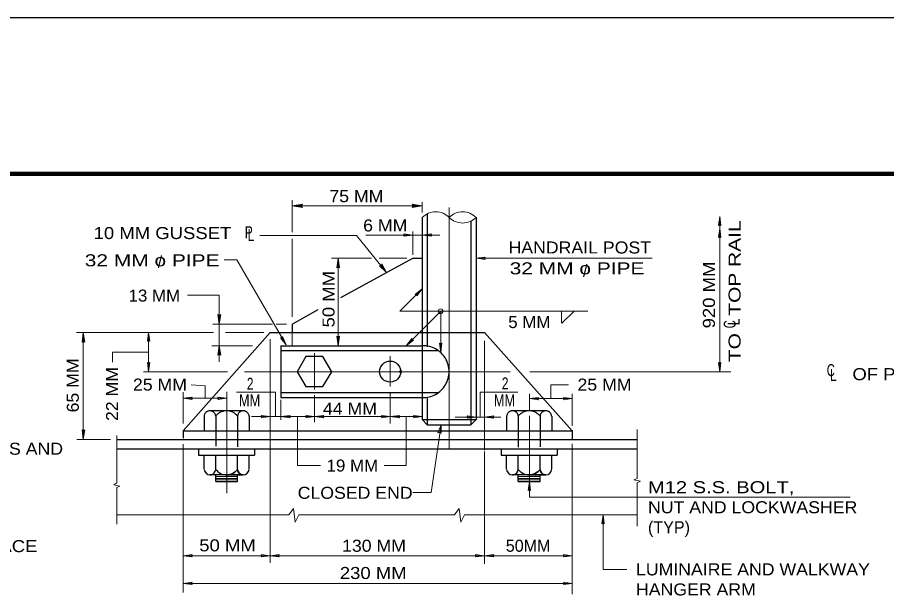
# Model space of a CAD drawing. Extents: x 312601.858 to 312602.699, y 144420.109 to 144420.704.
# Drawn here: x 312602.2633 to 312602.4801, y 144420.5593 to 144420.7035 of the extents above; entities that cross this region are included whole.
import ezdxf
from ezdxf.enums import TextEntityAlignment as Align

# ---------------------------------------------------------------- set-up
doc = ezdxf.new("R2010")
doc.units = 0
doc.header["$LTSCALE"] = 0.0012
doc.header["$PDMODE"] = 32
doc.header["$PDSIZE"] = 0.0006
for name, pattern in [('DOT_DASHED', [7.7, 5, -1.2, 0.3, -1.2]), ('LONG_DASHED', [7.5, 6, -1.5]), ('MEDIUM_DASHED', [4.5, 3, -1.5])]:
    doc.linetypes.add(name, pattern=pattern)
for name, color, linetype, lineweight in [('1', 7, 'Continuous', 13), ('2', 7, 'Continuous', 13), ('39', 7, 'Continuous', 13), ('4', 7, 'Continuous', 13)]:
    doc.layers.add(name, color=color, linetype=linetype, lineweight=lineweight)

msp = doc.modelspace()

# ---------------------------------------------------------------- hatches: boundary and pattern name
at = {"layer": '39'}
for points in [[(312602.3341, 144420.6565), (312602.3344, 144420.6561), (312602.3318, 144420.6565), (312602.3344, 144420.6569)], [(312602.3341, 144420.6565), (312602.3344, 144420.6561), (312602.3318, 144420.6565), (312602.3344, 144420.6569)], [(312602.362, 144420.6565), (312602.3618, 144420.6569), (312602.3643, 144420.6565), (312602.3618, 144420.6561)], [(312602.3433, 144420.6412), (312602.343, 144420.641), (312602.3433, 144420.6434), (312602.3436, 144420.641)], [(312602.354, 144420.6416), (312602.3542, 144420.642), (312602.3554, 144420.6399), (312602.3536, 144420.6415)], [(312602.3136, 144420.6292), (312602.314, 144420.6294), (312602.3136, 144420.627), (312602.3133, 144420.6294)], [(312602.2797, 144420.6227), (312602.2794, 144420.6225), (312602.2797, 144420.6249), (312602.2801, 144420.6225)], [(312602.3433, 144420.6238), (312602.3436, 144420.624), (312602.3433, 144420.6216), (312602.343, 144420.624)], [(312602.3433, 144420.6238), (312602.3436, 144420.624), (312602.3433, 144420.6216), (312602.343, 144420.624)], [(312602.3136, 144420.6194), (312602.3133, 144420.6192), (312602.3136, 144420.6216), (312602.314, 144420.6192)], [(312602.2797, 144420.6004), (312602.2801, 144420.6006), (312602.2797, 144420.5982), (312602.2794, 144420.6006)]]:
    msp.add_hatch(color=256, dxfattribs=at).paths.add_polyline_path(points)

# ---------------------------------------------------------------- linework, layer by layer
at = {"layer": '1'}
for p, q in [((312602.3318, 144420.6579), (312602.3318, 144420.6499)), ((312602.3318, 144420.6565), (312602.3643, 144420.6565)), ((312602.3643, 144420.6548), (312602.3643, 144420.6574)), ((312602.3619, 144420.6443), (312602.3619, 144420.6501)), ((312602.4385, 144420.6508), (312602.4385, 144420.6151)), ((312602.3238, 144420.6491), (312602.3479, 144420.6491)), ((312602.3318, 144420.6483), (312602.3318, 144420.6288)), ((312602.3479, 144420.6491), (312602.3554, 144420.6399)), ((312602.3416, 144420.6434), (312602.3516, 144420.6434)), ((312602.3433, 144420.6434), (312602.3433, 144420.6216)), ((312602.3535, 144420.6434), (312602.3604, 144420.6434)), ((312602.3777, 144420.6434), (312602.4216, 144420.6434)), ((312602.3149, 144420.643), (312602.318, 144420.643)), ((312602.318, 144420.643), (312602.3303, 144420.6218)), ((312602.3587, 144420.6302), (312602.3643, 144420.6358)), ((312602.3587, 144420.6302), (312602.4056, 144420.6302)), ((312602.3689, 144420.6302), (312602.3603, 144420.6216)), ((312602.3689, 144420.6301), (312602.3689, 144420.6199)), ((312602.399, 144420.6302), (312602.399, 144420.6272)), ((312602.3991, 144420.6272), (312602.4022, 144420.6302)), ((312602.3269, 144420.627), (312602.312, 144420.627)), ((312602.3304, 144420.627), (312602.3278, 144420.627)), ((312602.278, 144420.6249), (312602.3122, 144420.6249)), ((312602.2797, 144420.6249), (312602.2797, 144420.5982)), ((312602.296, 144420.6249), (312602.296, 144420.6152)), ((312602.3152, 144420.6249), (312602.3248, 144420.6249)), ((312602.3263, 144420.6232), (312602.3263, 144420.5952)), ((312602.3798, 144420.6228), (312602.3798, 144420.5955)), ((312602.287, 144420.62), (312602.287, 144420.6175)), ((312602.3118, 144420.6216), (312602.3219, 144420.6216)), ((312602.3136, 144420.6216), (312602.3136, 144420.6176)), ((312602.2947, 144420.6151), (312602.3157, 144420.6151)), ((312602.3911, 144420.6151), (312602.4413, 144420.6151)), ((312602.3046, 144420.61), (312602.3046, 144420.6022)), ((312602.3179, 144420.61), (312602.3277, 144420.61)), ((312602.3563, 144420.6097), (312602.3563, 144420.6022)), ((312602.3787, 144420.61), (312602.3881, 144420.61)), ((312602.391, 144420.6096), (312602.391, 144420.6055)), ((312602.4017, 144420.6096), (312602.4017, 144420.6016)), ((312602.3046, 144420.6085), (312602.3155, 144420.6085)), ((312602.329, 144420.6081), (312602.329, 144420.6031)), ((312602.391, 144420.6084), (312602.4017, 144420.6084)), ((312602.3563, 144420.6039), (312602.3643, 144420.6039)), ((312602.4179, 144420.6007), (312602.4179, 144420.5885)), ((312602.2781, 144420.5982), (312602.2865, 144420.5982)), ((312602.2881, 144420.5992), (312602.2881, 144420.5874)), ((312602.3046, 144420.597), (312602.3046, 144420.56)), ((312602.4017, 144420.5971), (312602.4017, 144420.5596)), ((312602.3263, 144420.5952), (312602.3263, 144420.5674)), ((312602.3798, 144420.5952), (312602.3798, 144420.5672)), ((312602.3155, 144420.5894), (312602.3196, 144420.5894)), ((312602.2873, 144420.5869), (312602.2881, 144420.5874)), ((312602.3128, 144420.589), (312602.3182, 144420.589)), ((312602.3128, 144420.5885), (312602.3182, 144420.5885)), ((312602.3128, 144420.5881), (312602.3182, 144420.5881)), ((312602.3882, 144420.589), (312602.3937, 144420.589)), ((312602.3882, 144420.5885), (312602.3937, 144420.5885)), ((312602.3882, 144420.5881), (312602.3937, 144420.5881)), ((312602.391, 144420.5877), (312602.391, 144420.5838)), ((312602.4171, 144420.5881), (312602.4179, 144420.5885)), ((312602.4171, 144420.5881), (312602.4187, 144420.5878)), ((312602.4179, 144420.5874), (312602.4187, 144420.5878)), ((312602.4179, 144420.5874), (312602.4179, 144420.5766)), ((312602.2873, 144420.5869), (312602.2888, 144420.5866)), ((312602.2881, 144420.5862), (312602.2888, 144420.5866)), ((312602.2881, 144420.5862), (312602.2881, 144420.5771)), ((312602.391, 144420.5838), (312602.471, 144420.5838)), ((312602.2881, 144420.5794), (312602.331, 144420.5794)), ((312602.3335, 144420.5794), (312602.3723, 144420.5794)), ((312602.3748, 144420.5794), (312602.4179, 144420.5794)), ((312602.4094, 144420.5794), (312602.4094, 144420.5658)), ((312602.4094, 144420.5658), (312602.4153, 144420.5658)), ((312602.3046, 144420.5623), (312602.4017, 144420.5623))]:
    msp.add_line(p, q, dxfattribs=at)
at = {"layer": '1', "linetype": 'LONG_DASHED', "lineweight": 25}
for p, q in [((312602.3655, 144420.6545), (312602.3655, 144420.6213)), ((312602.3764, 144420.6527), (312602.3764, 144420.6249)), ((312602.3643, 144420.6249), (312602.3643, 144420.6032)), ((312602.3764, 144420.6249), (312602.3764, 144420.6019)), ((312602.3777, 144420.6249), (312602.3777, 144420.6032)), ((312602.329, 144420.6216), (312602.329, 144420.6087)), ((312602.329, 144420.6216), (312602.3642, 144420.6216)), ((312602.329, 144420.6204), (312602.3683, 144420.6204)), ((312602.329, 144420.6099), (312602.3682, 144420.6099)), ((312602.329, 144420.6087), (312602.3643, 144420.6087)), ((312602.3655, 144420.6088), (312602.3655, 144420.6019)), ((312602.3128, 144420.604), (312602.3128, 144420.5965)), ((312602.3182, 144420.604), (312602.3182, 144420.5964)), ((312602.3643, 144420.6032), (312602.3655, 144420.6019)), ((312602.3643, 144420.6032), (312602.3777, 144420.6032)), ((312602.3764, 144420.6019), (312602.3777, 144420.6032)), ((312602.3882, 144420.604), (312602.3882, 144420.5963)), ((312602.3937, 144420.604), (312602.3937, 144420.5964)), ((312602.3046, 144420.6004), (312602.4016, 144420.6004)), ((312602.3655, 144420.6019), (312602.3764, 144420.6019))]:
    msp.add_line(p, q, dxfattribs=at)
at = {"layer": '1', "linetype": 'DOT_DASHED'}
for p, q in [((312602.371, 144420.6561), (312602.371, 144420.5959)), ((312602.3563, 144420.619), (312602.3563, 144420.6114)), ((312602.3199, 144420.6151), (312602.3862, 144420.6151)), ((312602.3155, 144420.6101), (312602.3155, 144420.5848)), ((312602.391, 144420.6041), (312602.391, 144420.5877))]:
    msp.add_line(p, q, dxfattribs=at)
at = {"layer": '1', "lineweight": 25}
for p, q in [((312602.3643, 144420.6536), (312602.3643, 144420.6249)), ((312602.3777, 144420.6536), (312602.3777, 144420.6249)), ((312602.344, 144420.6336), (312602.3619, 144420.6434)), ((312602.3619, 144420.6434), (312602.3643, 144420.6434)), ((312602.3318, 144420.627), (312602.3383, 144420.6306)), ((312602.3318, 144420.627), (312602.3318, 144420.6249)), ((312602.3046, 144420.6004), (312602.3263, 144420.6249)), ((312602.3263, 144420.6249), (312602.3798, 144420.6249)), ((312602.3798, 144420.6249), (312602.4017, 144420.6004)), ((312602.3046, 144420.6004), (312602.3046, 144420.5985)), ((312602.4017, 144420.6005), (312602.4017, 144420.5982)), ((312602.2881, 144420.5982), (312602.4179, 144420.5982)), ((312602.2881, 144420.5959), (312602.4179, 144420.5959)), ((312602.3224, 144420.5959), (312602.3224, 144420.5943)), ((312602.3979, 144420.5959), (312602.3979, 144420.5943)), ((312602.3099, 144420.5908), (312602.3099, 144420.5943)), ((312602.3128, 144420.5908), (312602.3128, 144420.5943)), ((312602.3182, 144420.5908), (312602.3182, 144420.5943)), ((312602.3211, 144420.5908), (312602.3211, 144420.5943)), ((312602.3853, 144420.5908), (312602.3853, 144420.5943)), ((312602.3882, 144420.5908), (312602.3882, 144420.5943)), ((312602.3937, 144420.5908), (312602.3937, 144420.5943)), ((312602.3966, 144420.5908), (312602.3966, 144420.5943)), ((312602.3128, 144420.5877), (312602.3128, 144420.5894)), ((312602.3182, 144420.5877), (312602.3182, 144420.5894)), ((312602.3882, 144420.5877), (312602.3882, 144420.5894)), ((312602.391, 144420.5894), (312602.3951, 144420.5894)), ((312602.3937, 144420.5877), (312602.3937, 144420.5894)), ((312602.3128, 144420.5877), (312602.3182, 144420.5877)), ((312602.3882, 144420.5877), (312602.3937, 144420.5877))]:
    msp.add_line(p, q, dxfattribs=at)
at = {"layer": '1', "linetype": 'LONG_DASHED'}
msp.add_line((312602.3318, 144420.6249), (312602.3318, 144420.6216), dxfattribs=at)
at = {"layer": '1', "linetype": 'MEDIUM_DASHED', "lineweight": 25}
for p, q in [((312602.3113, 144420.6054), (312602.3196, 144420.6054)), ((312602.3868, 144420.6054), (312602.3951, 144420.6054)), ((312602.3099, 144420.604), (312602.3099, 144420.6004)), ((312602.3211, 144420.604), (312602.3211, 144420.6004)), ((312602.3853, 144420.604), (312602.3853, 144420.6004)), ((312602.3966, 144420.604), (312602.3966, 144420.6004))]:
    msp.add_line(p, q, dxfattribs=at)
at = {"layer": '1'}
for points in [[(312602.4382, 144420.6516), (312602.4385, 144420.6538), (312602.4388, 144420.6516), (312602.4385, 144420.6518)], [(312602.4382, 144420.6486), (312602.4385, 144420.6508), (312602.4388, 144420.6486), (312602.4385, 144420.6488)], [(312602.3597, 144420.6495), (312602.3619, 144420.6492), (312602.3597, 144420.6489), (312602.3599, 144420.6492)], [(312602.3666, 144420.6489), (312602.3643, 144420.6492), (312602.3666, 144420.6495), (312602.3663, 144420.6492)], [(312602.38, 144420.6431), (312602.3777, 144420.6434), (312602.38, 144420.6437), (312602.3797, 144420.6434)], [(312602.3625, 144420.6344), (312602.3643, 144420.6358), (312602.3629, 144420.634), (312602.3629, 144420.6344)], [(312602.2957, 144420.6227), (312602.296, 144420.6249), (312602.2963, 144420.6227), (312602.296, 144420.6229)], [(312602.3294, 144420.6239), (312602.3303, 144420.6218), (312602.3289, 144420.6236), (312602.3293, 144420.6236)], [(312602.3621, 144420.623), (312602.3603, 144420.6216), (312602.3617, 144420.6234), (312602.3617, 144420.623)], [(312602.3692, 144420.6222), (312602.3689, 144420.6199), (312602.3686, 144420.6222), (312602.3689, 144420.6219)], [(312602.2963, 144420.6174), (312602.296, 144420.6151), (312602.2957, 144420.6174), (312602.296, 144420.6171)], [(312602.4388, 144420.6174), (312602.4385, 144420.6151), (312602.4382, 144420.6174), (312602.4385, 144420.6171)], [(312602.3069, 144420.6082), (312602.3046, 144420.6085), (312602.3069, 144420.6088), (312602.3066, 144420.6085)], [(312602.3133, 144420.6088), (312602.3155, 144420.6085), (312602.3133, 144420.6082), (312602.3135, 144420.6085)], [(312602.3933, 144420.6081), (312602.391, 144420.6084), (312602.3933, 144420.6087), (312602.393, 144420.6084)], [(312602.3995, 144420.6087), (312602.4017, 144420.6084), (312602.3995, 144420.6081), (312602.3997, 144420.6084)], [(312602.3241, 144420.6042), (312602.3263, 144420.6039), (312602.3241, 144420.6036), (312602.3243, 144420.6039)], [(312602.3313, 144420.6036), (312602.329, 144420.6039), (312602.3313, 144420.6042), (312602.331, 144420.6039)], [(312602.3352, 144420.6042), (312602.3374, 144420.6039), (312602.3352, 144420.6036), (312602.3354, 144420.6039)], [(312602.3397, 144420.6036), (312602.3374, 144420.6039), (312602.3397, 144420.6042), (312602.3394, 144420.6039)], [(312602.3541, 144420.6042), (312602.3563, 144420.6039), (312602.3541, 144420.6036), (312602.3543, 144420.6039)], [(312602.3586, 144420.6036), (312602.3563, 144420.6039), (312602.3586, 144420.6042), (312602.3583, 144420.6039)], [(312602.3621, 144420.6042), (312602.3643, 144420.6039), (312602.3621, 144420.6036), (312602.3623, 144420.6039)], [(312602.3755, 144420.6041), (312602.3777, 144420.6038), (312602.3755, 144420.6035), (312602.3757, 144420.6038)], [(312602.3821, 144420.6035), (312602.3798, 144420.6038), (312602.3821, 144420.6041), (312602.3818, 144420.6038)], [(312602.3682, 144420.5999), (312602.369, 144420.6019), (312602.369, 144420.5998), (312602.3687, 144420.6)], [(312602.3907, 144420.5855), (312602.391, 144420.5877), (312602.3913, 144420.5855), (312602.391, 144420.5857)], [(312602.4091, 144420.5772), (312602.4094, 144420.5794), (312602.4097, 144420.5772), (312602.4094, 144420.5774)], [(312602.3069, 144420.5689), (312602.3046, 144420.5692), (312602.3069, 144420.5695), (312602.3066, 144420.5692)], [(312602.3241, 144420.5695), (312602.3263, 144420.5692), (312602.3241, 144420.5689), (312602.3243, 144420.5692)], [(312602.3286, 144420.5689), (312602.3263, 144420.5692), (312602.3286, 144420.5695), (312602.3283, 144420.5692)], [(312602.3776, 144420.5695), (312602.3798, 144420.5692), (312602.3776, 144420.5689), (312602.3778, 144420.5692)], [(312602.3821, 144420.5689), (312602.3798, 144420.5692), (312602.3821, 144420.5695), (312602.3818, 144420.5692)], [(312602.3995, 144420.5695), (312602.4017, 144420.5692), (312602.3995, 144420.5689), (312602.3997, 144420.5692)], [(312602.3069, 144420.562), (312602.3046, 144420.5623), (312602.3069, 144420.5626), (312602.3066, 144420.5623)], [(312602.3995, 144420.5626), (312602.4017, 144420.5623), (312602.3995, 144420.562), (312602.3997, 144420.5623)]]:
    msp.add_lwpolyline(points, close=True, dxfattribs=at)
for points in [[(312602.3502, 144420.6492), (312602.3619, 144420.6492), (312602.3643, 144420.6492), (312602.3687, 144420.6492)], [(312602.3136, 144420.6342), (312602.3136, 144420.627), (312602.3136, 144420.6216)], [(312602.3589, 144420.6151), (312602.3593, 144420.6151), (312602.3592, 144420.6151)], [(312602.3217, 144420.6039), (312602.3263, 144420.6039), (312602.329, 144420.6039)], [(312602.329, 144420.6039), (312602.3374, 144420.6039), (312602.3563, 144420.6039), (312602.3563, 144420.6039)], [(312602.3725, 144420.6038), (312602.3777, 144420.6038), (312602.3798, 144420.6038), (312602.3839, 144420.6038)], [(312602.369, 144420.6019), (312602.3665, 144420.585), (312602.3619, 144420.585)], [(312602.331, 144420.5794), (312602.3322, 144420.581), (312602.3326, 144420.5776), (312602.3335, 144420.5794)], [(312602.3723, 144420.5794), (312602.3735, 144420.581), (312602.3739, 144420.5776), (312602.3748, 144420.5794)], [(312602.3046, 144420.5692), (312602.3263, 144420.5692), (312602.3798, 144420.5692), (312602.4017, 144420.5692)]]:
    msp.add_lwpolyline(points, dxfattribs=at)
at = {"layer": '1', "lineweight": 25}
msp.add_lwpolyline([(312602.3352, 144420.6114), (312602.3395, 144420.6114), (312602.3417, 144420.6151), (312602.3395, 144420.6189), (312602.3352, 144420.6189), (312602.3331, 144420.6151)], close=True, dxfattribs=at)
for points in [[(312602.3085, 144420.5959), (312602.3085, 144420.5943), (312602.3224, 144420.5943)], [(312602.384, 144420.5959), (312602.384, 144420.5943), (312602.3979, 144420.5943)], [(312602.3155, 144420.5894), (312602.3113, 144420.5894), (312602.3116, 144420.5894)], [(312602.391, 144420.5894), (312602.3868, 144420.5894), (312602.387, 144420.5894)]]:
    msp.add_lwpolyline(points, dxfattribs=at)
at = {"layer": '1', "lineweight": 35}
for points in [[(312602.3155, 144420.5894), (312602.3196, 144420.5894), (312602.3194, 144420.5894)], [(312602.391, 144420.5894), (312602.3951, 144420.5894), (312602.3949, 144420.5894)]]:
    msp.add_lwpolyline(points, dxfattribs=at)
at = {"layer": '1'}
msp.add_circle((312602.36885, 144420.63019), 0.000595, dxfattribs=at)
at = {"layer": '1', "lineweight": 25}
msp.add_circle((312602.35627, 144420.615145), 0.002635, dxfattribs=at)
at = {"layer": '1', "linetype": 'LONG_DASHED', "lineweight": 25}
msp.add_arc((312602.36451, 144420.615145), 0.006465, 267.78238, 92.21762, dxfattribs=at)
at = {"layer": '1', "linetype": 'MEDIUM_DASHED', "lineweight": 25}
for centre, radius, start, end in [((312602.311305, 144420.603922), 0.001448, 3.47141, 176.52859), ((312602.31547, 144420.60197), 0.0034, 36.8699, 143.1301), ((312602.319635, 144420.603922), 0.001448, 3.47141, 176.52859), ((312602.386785, 144420.603922), 0.001448, 3.47141, 176.52859), ((312602.39095, 144420.60197), 0.0034, 36.8699, 143.1301), ((312602.395115, 144420.603922), 0.001448, 3.47141, 176.52859)]:
    msp.add_arc(centre, radius, start, end, dxfattribs=at)
at = {"layer": '1', "lineweight": 25}
for centre, radius, start, end in [((312602.311305, 144420.590838), 0.001448, 280.13588, 356.52859), ((312602.31547, 144420.59279), 0.0034, 216.8699, 270), ((312602.319635, 144420.590838), 0.001448, 183.47141, 356.52859), ((312602.386785, 144420.590838), 0.001448, 183.47141, 270), ((312602.386785, 144420.590838), 0.001448, 280.13588, 356.52859), ((312602.39095, 144420.59279), 0.0034, 216.8699, 270), ((312602.395115, 144420.590838), 0.001448, 183.47141, 356.52859)]:
    msp.add_arc(centre, radius, start, end, dxfattribs=at)
at = {"layer": '1'}
for centre in [(312602.31547, 144420.59279), (312602.39095, 144420.59279)]:
    msp.add_arc(centre, 0.0034, 269.99962, 323.1301, dxfattribs=at)
at = {"layer": '1', "lineweight": 35}
for centre, radius, start, end in [((312602.31547, 144420.59279), 0.0034, 270, 323.1301), ((312602.319635, 144420.590838), 0.001448, 183.47141, 259.86412), ((312602.39095, 144420.59279), 0.0034, 270, 323.1301), ((312602.395115, 144420.590838), 0.001448, 183.47141, 259.86412)]:
    msp.add_arc(centre, radius, start, end, dxfattribs=at)
at = {"layer": '1', "lineweight": 25}
msp.add_ellipse((312602.311305, 144420.590838), major_axis=(0.000088, -0.001445), ratio=0.974511, start_param=4.712389, end_param=6.2225978, dxfattribs=at)
at = {"layer": '1'}
msp.add_point((312602.3589, 144420.6151), dxfattribs=at)
at = {"layer": '2'}
for p, q in [((312602.4385, 144420.6508), (312602.4385, 144420.6538)), ((312602.3136, 144420.6342), (312602.3057, 144420.6342)), ((312602.296, 144420.62), (312602.287, 144420.62)), ((312602.4008, 144420.6118), (312602.3964, 144420.6118)), ((312602.3964, 144420.6084), (312602.3964, 144420.6118)), ((312602.3277, 144420.6039), (312602.3277, 144420.61)), ((312602.3374, 144420.6093), (312602.3374, 144420.6025)), ((312602.3787, 144420.6038), (312602.3787, 144420.61)), ((312602.3332, 144420.6039), (312602.3332, 144420.5917)), ((312602.3603, 144420.6039), (312602.3603, 144420.5917)), ((312602.3332, 144420.5917), (312602.3389, 144420.5917)), ((312602.3548, 144420.5917), (312602.3603, 144420.5917))]:
    msp.add_line(p, q, dxfattribs=at)
at = {"layer": '2', "linetype": 'DOT_DASHED'}
msp.add_line((312602.3374, 144420.6197), (312602.3374, 144420.6107), dxfattribs=at)
at = {"layer": '2'}
msp.add_lwpolyline([(312602.3101, 144420.6085), (312602.3101, 144420.6116), (312602.3066, 144420.6118)], dxfattribs=at)
at = {"layer": '39', "lineweight": 25}
msp.add_line((312601.8578, 144420.7035), (312602.6988, 144420.7035), dxfattribs=at)
at = {"layer": '39', "lineweight": 158}
msp.add_line((312601.9088, 144420.6645), (312602.6838, 144420.6645), dxfattribs=at)
at = {"layer": '39'}
for points in [[(312602.3341, 144420.6565), (312602.3344, 144420.6561), (312602.3318, 144420.6565), (312602.3344, 144420.6569)], [(312602.3341, 144420.6565), (312602.3344, 144420.6561), (312602.3318, 144420.6565), (312602.3344, 144420.6569)], [(312602.362, 144420.6565), (312602.3618, 144420.6569), (312602.3643, 144420.6565), (312602.3618, 144420.6561)], [(312602.3433, 144420.6412), (312602.343, 144420.641), (312602.3433, 144420.6434), (312602.3436, 144420.641)], [(312602.354, 144420.6416), (312602.3542, 144420.642), (312602.3554, 144420.6399), (312602.3536, 144420.6415)], [(312602.3136, 144420.6292), (312602.314, 144420.6294), (312602.3136, 144420.627), (312602.3133, 144420.6294)], [(312602.2797, 144420.6227), (312602.2794, 144420.6225), (312602.2797, 144420.6249), (312602.2801, 144420.6225)], [(312602.3433, 144420.6238), (312602.3436, 144420.624), (312602.3433, 144420.6216), (312602.343, 144420.624)], [(312602.3433, 144420.6238), (312602.3436, 144420.624), (312602.3433, 144420.6216), (312602.343, 144420.624)], [(312602.3136, 144420.6194), (312602.3133, 144420.6192), (312602.3136, 144420.6216), (312602.314, 144420.6192)], [(312602.2797, 144420.6004), (312602.2801, 144420.6006), (312602.2797, 144420.5982), (312602.2794, 144420.6006)]]:
    msp.add_lwpolyline(points, close=True, dxfattribs=at)
at = {"layer": '4'}
for centre, start, end in [((312602.36765, 144420.650293), 44.63115, 135.36885), ((312602.37435, 144420.650293), 44.63115, 135.36885), ((312602.37435, 144420.656907), 224.63115, 315.36885)]:
    msp.add_arc(centre, 0.004707, start, end, dxfattribs=at)

# ---------------------------------------------------------------- texts
at = {"layer": '2'}
for s, width, p in [('75 MM', 1.1, (312602.34785, 144420.6574)), ('6 MM', 1.1, (312602.35505, 144420.6501)), ('32 MM o PIPE', 1.3, (312602.2969, 144420.6414)), ('32 MM o PIPE', 1.3, (312602.4029, 144420.6394)), ('13 MM', 1.05, (312602.29745, 144420.6326)), ('5 MM', 1.05, (312602.391, 144420.626)), ('25 MM', 1.1, (312602.29885, 144420.6104)), ('2', 0.75, (312602.32135, 144420.6106)), ('2', 0.75, (312602.38495, 144420.6107)), ('25 MM', 1.1, (312602.40975, 144420.6104)), ('MM', 0.8, (312602.3212, 144420.6065)), ('MM', 0.8, (312602.3848, 144420.6065)), ('44 MM', 1.1, (312602.34625, 144420.6044)), ('19 MM', 1.05, (312602.34685, 144420.5902)), ('SIGN PANEL FACE', 1.15, (312602.24765, 144420.5701)), ('50 MM', 1.15, (312602.3157, 144420.5703)), ('130 MM', 1.1, (312602.35225, 144420.5702)), ('230 MM', 1.15, (312602.35205, 144420.5634))]:
    msp.add_text(s, height=0.003, dxfattribs=dict(at, width=width)).set_placement(p, align=Align.CENTER)
at = {"layer": '2', "width": 1.3}
msp.add_text('TO   TOP RAIL', height=0.003, rotation=90, dxfattribs=at).set_placement((312602.4437, 144420.6175))
at = {"layer": '2'}
for s, width, p in [('10 MM GUSSET', 1.15, (312602.2823, 144420.6482)), ('P', 0.75, (312602.32, 144420.6484)), ('L', 0.75, (312602.3207, 144420.6477)), ('HANDRAIL POST', 1.1, (312602.3858, 144420.6446)), ('C', 0.7, (312602.4652, 144420.614)), ('L', 0.75, (312602.466, 144420.6128)), ('OF PIPE', 1.15, (312602.4716, 144420.613)), ('WITH LOCKNUTS AND', 1.1, (312602.2276, 144420.5944)), ('M12 S.S. BOLT,', 1.25, (312602.4206, 144420.5848)), ('CLOSED END', 1.1, (312602.3332, 144420.5834)), ('NUT AND LOCKWASHER ', 1.1, (312602.4206, 144420.5798)), ('LUMINAIRE AND WALKWAY', 1.1, (312602.4176, 144420.5643)), ('HANGER ARM ', 1.1, (312602.4176, 144420.5593))]:
    msp.add_text(s, height=0.003, dxfattribs=dict(at, width=width)).set_placement(p)
for s, p in [('/', (312602.29885, 144420.641)), ('/', (312602.40495, 144420.6388)), ('50MM', (312602.3907, 144420.5702))]:
    msp.add_text(s, height=0.003, dxfattribs=at).set_placement(p, align=Align.CENTER)
for s, height, width, p in [('920 MM', 0.003, 1.15, (312602.4373, 144420.63425)), ('50 MM', 0.003, 1.15, (312602.3424, 144420.6332)), ('L', 0.002999, 0.75, (312602.4435, 144420.62755)), ('C', 0.002999, 0.7, (312602.4425, 144420.62695)), ('65 MM', 0.003, 1.1, (312602.2786, 144420.6117)), ('22 MM', 0.003, 1.1, (312602.2884, 144420.60955))]:
    msp.add_text(s, height=height, rotation=90, dxfattribs=dict(at, width=width)).set_placement(p, align=Align.CENTER)
msp.add_text('(TYP)', height=0.003, dxfattribs=at).set_placement((312602.4206, 144420.5748))

doc.saveas('drawing.dxf')
